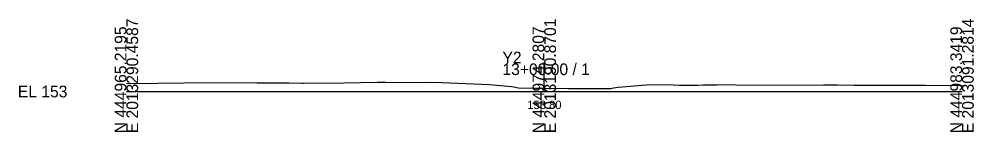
# Model space of a CAD drawing. Extents: x -26 to 203, y -10 to 6017.
# Drawn here: x -25.7 to 202.8, y 5990.3 to 6017.4 of the extents above; entities that cross this region are included whole.
import ezdxf

# ---------------------------------------------------------------- set-up
doc = ezdxf.new("R2010")
doc.units = 0
for name, color, linetype in [('Default', 7, 'Continuous'), ('Exist Cross Section Cell', 7, 'Continuous'), ('Exist XS Center Line Elevation Label', 7, 'Continuous'), ('Exist XS Ground Line', 7, 'Continuous')]:
    doc.layers.add(name, color=color, linetype=linetype)

msp = doc.modelspace()

# ---------------------------------------------------------------- linework, layer by layer
at = {"layer": 'Exist Cross Section Cell'}
for p, q in [((100, 6000), (100, 6006.74)), ((0, 6000), (100, 6000)), ((100, 6000), (200, 6000))]:
    msp.add_line(p, q, dxfattribs=at)
at = {"layer": 'Exist XS Ground Line'}
msp.add_lwpolyline([(0, 6001.91), (7.52, 6002.02), (13.74, 6002.1), (21.83, 6002.16), (31.3, 6002.09), (31.95, 6002.09), (38.94, 6002.05), (41.97, 6002.04), (42.28, 6002.04), (52.02, 6002.12), (60.13, 6002.23), (62.06, 6002.22), (69.33, 6002.2), (72.1, 6002.25), (75.42, 6002.2), (86.91, 6001.69), (92.16, 6001.22), (92.72, 6001.14), (93.85, 6000.88), (97.37, 6000.82), (100, 6000.8), (105.82, 6000.76), (111.71, 6000.73), (115.96, 6000.71), (116.56, 6000.86), (117.71, 6001.04), (124.4, 6001.57), (126.44, 6001.66), (130.82, 6001.59), (132.34, 6001.56), (135.44, 6001.52), (135.97, 6001.52), (136.74, 6001.51), (138.02, 6001.57), (139.62, 6001.61), (141.32, 6001.64), (143.77, 6001.69), (145.85, 6001.63), (163.88, 6001.56), (166.83, 6001.57), (170.23, 6001.58), (174.17, 6001.56), (191.23, 6001.53), (200, 6001.47)], dxfattribs=at)

# ---------------------------------------------------------------- texts
at = {"layer": 'Default'}
msp.add_text('-', height=0.0001, dxfattribs=at).set_placement((0, 6000))
at = {"layer": 'Exist Cross Section Cell'}
for s, p in [('E 2013290.4587', (2.8, 5990)), ('E 2013190.8701', (102.8, 5990)), ('E 2013091.2814', (202.8, 5990)), ('N 444965.2195', (0, 5990)), ('N 444974.2807', (100, 5990)), ('N 444983.3419', (200, 5990))]:
    msp.add_text(s, height=2.8, rotation=90, dxfattribs=at).set_placement(p)
for s, p in [('Y2', (90, 6006.74)), ('13+00.00 / 1', (90, 6003.94)), ('EL 153', (-26, 5998.6))]:
    msp.add_text(s, height=2.8, dxfattribs=at).set_placement(p)
at = {"layer": 'Exist XS Center Line Elevation Label'}
msp.add_text('153.80', height=2, dxfattribs=at).set_placement((95.95, 5995.8))

doc.saveas('drawing.dxf')
